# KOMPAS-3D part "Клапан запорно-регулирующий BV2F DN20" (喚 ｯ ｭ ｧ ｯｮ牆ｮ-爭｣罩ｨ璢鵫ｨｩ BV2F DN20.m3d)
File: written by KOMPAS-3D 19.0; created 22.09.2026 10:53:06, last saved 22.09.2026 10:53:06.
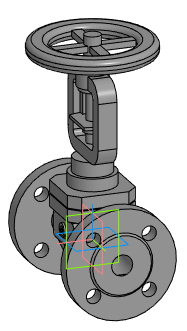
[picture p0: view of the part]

Document properties: Автор: Энергия; Полное имя файла: Z:\3.Личные\sachek\Dendor\_3D для проектировщиков\5.7 Клапан запорно-регулирующий BV2F\BV2F_STP\Клапан запорно-регулирующий BV2F DN20.m3d

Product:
- Part/product: Клапан запорно-регулирующий BV2F DN20

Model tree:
1. Операция без истории:1  (labels: Клапан запорно-регулирующий BV2F DN20)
